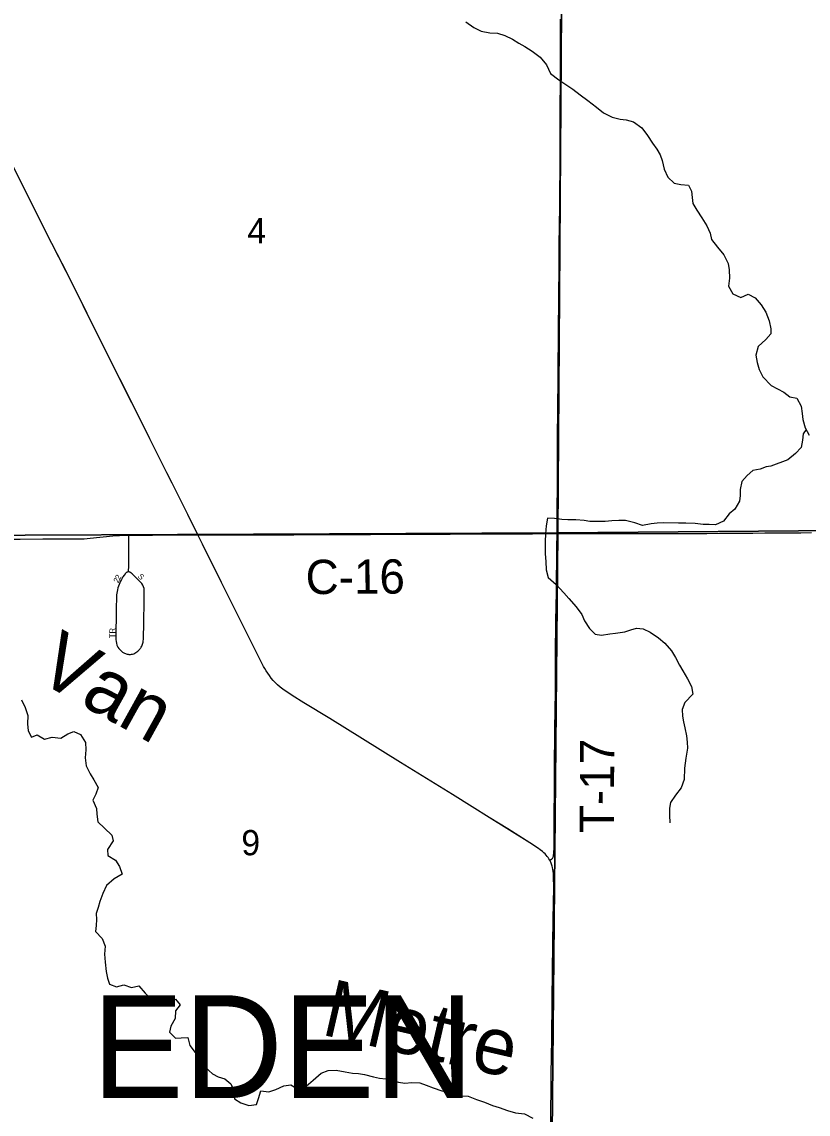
# Model space of a CAD drawing. Extents: x 0 to 34, y 0 to 22.
# Drawn here: x 6.531 to 7.184, y 16.419 to 17.325 of the extents above; entities that cross this region are included whole.
import ezdxf

# ---------------------------------------------------------------- set-up
doc = ezdxf.new("R2010")
doc.units = 0
for name, color, linetype in [('Default', 7, 'Continuous'), ('GM_X_County_Road', 7, 'Continuous'), ('GM_X_County_Road_Text', 7, 'Continuous'), ('GM_X_Minor_River', 7, 'Continuous'), ('GM_X_Minor_River_Text', 7, 'Continuous'), ('GM_X_Section', 7, 'Continuous'), ('GM_X_Section_Text', 7, 'Continuous'), ('GM_X_State_Route', 7, 'Continuous'), ('GM_X_Township_Road', 7, 'Continuous'), ('GM_X_Township_Road_Text', 7, 'Continuous'), ('GM_X_Township_Subdivision', 7, 'Continuous'), ('GM_X_Township_Subdivision_Text', 7, 'Continuous'), ('GM_X_Township_Text', 7, 'Continuous')]:
    doc.layers.add(name, color=color, linetype=linetype)

msp = doc.modelspace()

# ---------------------------------------------------------------- linework, layer by layer
at = {"layer": 'Default'}
for points in [[(6.91883, 16.66544), (6.9048, 16.67409), (6.88846, 16.6843), (6.84537, 16.71094), (6.81393, 16.73042), (6.78677, 16.74735), (6.76527, 16.76044), (6.75546, 16.76648), (6.7478, 16.77167), (6.74556, 16.77341), (6.74352, 16.7752), (6.74185, 16.77684), (6.73992, 16.77887), (6.73824, 16.78079), (6.73664, 16.7829), (6.73525, 16.78496), (6.73408, 16.78675), (6.73286, 16.78871), (6.73182, 16.79045), (6.73097, 16.79206), (6.72699, 16.79994), (6.72252, 16.80879), (6.71822, 16.81742), (6.71488, 16.82408), (6.70988, 16.8341), (6.7025, 16.84894), (6.69702, 16.85996), (6.68994, 16.87423), (6.68404, 16.88612), (6.68111, 16.89197), (6.67731, 16.89961), (6.6689, 16.91658), (6.66233, 16.92968), (6.65593, 16.94252), (6.65174, 16.95091), (6.6375, 16.9793), (6.62776, 16.99872), (6.59751, 17.059), (6.57379, 17.10651), (6.55629, 17.14119), (6.53311, 17.18728), (6.52382, 17.20557)], [(6.97007, 16.40192), (6.97021, 16.4214), (6.97034, 16.44107), (6.97042, 16.4528), (6.97093, 16.48138), (6.97129, 16.51432), (6.97169, 16.56094), (6.97196, 16.58083), (6.97247, 16.60756), (6.97241, 16.61624), (6.97231, 16.61859), (6.97208, 16.62085), (6.97187, 16.62233), (6.97156, 16.62388), (6.97129, 16.62494), (6.97101, 16.62593), (6.97049, 16.62738), (6.9699, 16.62876), (6.96932, 16.62986), (6.96855, 16.63115), (6.96789, 16.63213), (6.96713, 16.63312), (6.96628, 16.63411), (6.96529, 16.63516), (6.96423, 16.63617), (6.96303, 16.63721), (6.96135, 16.63847), (6.95981, 16.6396), (6.95256, 16.64437), (6.93429, 16.65584), (6.91883, 16.66544)]]:
    msp.add_lwpolyline(points, dxfattribs=at)
at = {"layer": 'GM_X_County_Road'}
for points in [[(6.47162, 16.8974), (6.47313, 16.89712), (6.47501, 16.89685), (6.47643, 16.89667), (6.47767, 16.89652), (6.47946, 16.89634), (6.48126, 16.89619), (6.48339, 16.89608), (6.48643, 16.89593), (6.49157, 16.89586), (6.50071, 16.89594), (6.52992, 16.8961), (6.54887, 16.89625), (6.56099, 16.89624), (6.57653, 16.89625), (6.58303, 16.89641), (6.58796, 16.89676), (6.60683, 16.89871), (6.61243, 16.89907), (6.62003, 16.89925)], [(6.62003, 16.89925), (6.62456, 16.89935), (6.63978, 16.89939), (6.65094, 16.89953), (6.67117, 16.89958), (6.67556, 16.89959), (6.67731, 16.89961)], [(6.67731, 16.89961), (6.69531, 16.89963), (6.71149, 16.89965), (6.73144, 16.89955), (6.75684, 16.89966), (6.76959, 16.8998), (6.79388, 16.89988), (6.82056, 16.89997), (6.85258, 16.90027), (6.88646, 16.90029), (6.90449, 16.90039), (6.92096, 16.90037), (6.94022, 16.90045), (6.95482, 16.90052), (6.9754, 16.90057)], [(6.9754, 16.90057), (6.98031, 16.90059), (6.99678, 16.90076), (7.01917, 16.90073), (7.04154, 16.90075), (7.07325, 16.90079), (7.08537, 16.90081), (7.09034, 16.9008), (7.09936, 16.90081), (7.10992, 16.9009), (7.11645, 16.90093), (7.12204, 16.90096), (7.12732, 16.90101), (7.1326, 16.90107), (7.13757, 16.9011), (7.14749, 16.90114), (7.16111, 16.90116), (7.16916, 16.90122), (7.17752, 16.90137), (7.18621, 16.90148)]]:
    msp.add_lwpolyline(points, dxfattribs=at)
at = {"layer": 'GM_X_Minor_River'}
for points in [[(6.89965, 17.3248), (6.90626, 17.32001), (6.91231, 17.31693), (6.91951, 17.31555), (6.92596, 17.31531), (6.93201, 17.31337), (6.93825, 17.31029), (6.94354, 17.30702), (6.94846, 17.30433), (6.9545, 17.30049), (6.96129, 17.2955), (6.96637, 17.28921), (6.96992, 17.28197), (6.97671, 17.27661), (6.98181, 17.27353), (6.98823, 17.26893), (6.99446, 17.26433), (7.00087, 17.25954), (7.00785, 17.25399), (7.0137, 17.24939), (7.02107, 17.24573), (7.02751, 17.24416), (7.03244, 17.24356), (7.03869, 17.2418), (7.04548, 17.23682), (7.05018, 17.23052), (7.0543, 17.22423), (7.05787, 17.21927), (7.06087, 17.21451)], [(7.06087, 17.21451), (7.06236, 17.20975), (7.06401, 17.20272), (7.067, 17.19606), (7.07246, 17.19109), (7.07796, 17.18991), (7.08421, 17.18929), (7.08665, 17.18453), (7.08736, 17.17921), (7.08771, 17.17409), (7.09108, 17.16856), (7.09521, 17.16246), (7.09952, 17.1556), (7.10213, 17.14951), (7.10342, 17.14438), (7.10831, 17.13789), (7.11357, 17.13159), (7.11713, 17.12436), (7.11785, 17.11923), (7.11817, 17.11221), (7.11755, 17.10558), (7.12111, 17.09929), (7.12773, 17.09639), (7.13382, 17.099), (7.13949, 17.09612), (7.14457, 17.0902), (7.14832, 17.0841), (7.15112, 17.07706), (7.15244, 17.07034), (7.15244, 17.06628), (7.14834, 17.06153), (7.14204, 17.05569), (7.14009, 17.0485), (7.14118, 17.04242), (7.14285, 17.03672), (7.14602, 17.03044), (7.1529, 17.0234)], [(7.1529, 17.0234), (7.16324, 17.01773), (7.16816, 17.01411), (7.17423, 17.01294), (7.17761, 17.00629), (7.17854, 17.00003), (7.17908, 16.99509), (7.18114, 16.98825), (7.18434, 16.98217)], [(7.18179, 16.98702), (7.17922, 16.98333), (7.17882, 16.97802), (7.17765, 16.97195), (7.17289, 16.96704), (7.1666, 16.96175), (7.15242, 16.95642)], [(7.15242, 16.95642), (7.14869, 16.95587), (7.14375, 16.95401), (7.13767, 16.95292), (7.13289, 16.94879), (7.12849, 16.94389), (7.12711, 16.93707), (7.12708, 16.93233), (7.12647, 16.92759), (7.12263, 16.92098), (7.11786, 16.91703), (7.11326, 16.911), (7.10659, 16.90783), (7.10147, 16.90805), (7.09654, 16.90828), (7.0899, 16.9089), (7.08213, 16.90915), (7.07587, 16.90938), (7.06316, 16.90948), (7.05822, 16.90933), (7.05329, 16.9088), (7.04606, 16.90733), (7.03963, 16.90947), (7.03187, 16.91161), (7.02636, 16.91146), (7.02067, 16.91113), (7.01516, 16.9106), (7.00245, 16.9107), (6.99771, 16.91149), (6.99089, 16.91192), (6.98406, 16.91216), (6.97913, 16.91239), (6.97306, 16.91319), (6.96718, 16.91343), (6.96618, 16.90699), (6.96557, 16.90035), (6.96533, 16.8941), (6.96548, 16.88935), (6.96544, 16.88385), (6.96596, 16.8774), (6.9661, 16.87057), (6.96795, 16.8643), (6.97455, 16.85856), (6.98076, 16.85149), (6.9849, 16.84672), (6.99111, 16.84004), (6.9958, 16.83355), (6.99804, 16.82842), (7.00216, 16.82194), (7.00687, 16.81716), (7.01199, 16.81636), (7.01902, 16.81764), (7.02377, 16.81817), (7.03155, 16.81925), (7.03631, 16.82092), (7.04125, 16.82221), (7.04656, 16.82179), (7.05242, 16.8189), (7.05941, 16.81411), (7.06449, 16.80971), (7.07014, 16.80341), (7.07351, 16.79807), (7.07688, 16.7916), (7.0795, 16.78683), (7.08344, 16.78017), (7.08661, 16.77388), (7.08789, 16.76743), (7.0812, 16.76065), (7.07907, 16.75479), (7.07941, 16.74928), (7.08013, 16.74454), (7.08123, 16.7396), (7.0827, 16.73295), (7.08323, 16.72782), (7.08338, 16.7227), (7.08218, 16.71437), (7.08098, 16.70622), (7.08053, 16.69674), (7.0782, 16.68993), (7.07361, 16.68389), (7.06939, 16.67786), (7.0684, 16.67293), (7.06855, 16.66724), (7.06869, 16.66079)], [(6.531, 16.76271), (6.53418, 16.75642), (6.5364, 16.74977), (6.53616, 16.74294), (6.5365, 16.73725), (6.53931, 16.73192), (6.54406, 16.73378), (6.55011, 16.73013), (6.55638, 16.73198), (6.56377, 16.73097), (6.56949, 16.73453), (6.57444, 16.73658), (6.58011, 16.73408), (6.58424, 16.7276), (6.58438, 16.72152), (6.58377, 16.71489), (6.58466, 16.70806), (6.58803, 16.70158), (6.59103, 16.69644), (6.59477, 16.69015), (6.59284, 16.68467), (6.59033, 16.67975), (6.59332, 16.6729), (6.59366, 16.66797), (6.59437, 16.6617), (6.60002, 16.65654), (6.60605, 16.6508), (6.60696, 16.64587), (6.60236, 16.63888), (6.6027, 16.63376), (6.60893, 16.62992), (6.61231, 16.62477), (6.61454, 16.61831), (6.60787, 16.61456), (6.60157, 16.60892), (6.59848, 16.6023), (6.59597, 16.59568), (6.5946, 16.59076), (6.59286, 16.58584), (6.5932, 16.58072), (6.59297, 16.57579), (6.59237, 16.57086), (6.59801, 16.56513), (6.60043, 16.55866), (6.59981, 16.55203), (6.60052, 16.54539), (6.60142, 16.53779), (6.60251, 16.53228), (6.60418, 16.52715), (6.60986, 16.52502), (6.61594, 16.52668), (6.62219, 16.52455), (6.62846, 16.52583), (6.63354, 16.51972)], [(6.63354, 16.51972), (6.63938, 16.51418), (6.64678, 16.51526), (6.65322, 16.51388), (6.65873, 16.51479), (6.66268, 16.51002), (6.65866, 16.50512), (6.65842, 16.49867), (6.65496, 16.49243), (6.65379, 16.48732), (6.65868, 16.48254), (6.66362, 16.4827), (6.66893, 16.48304), (6.67059, 16.47638), (6.6751, 16.47047), (6.67998, 16.46398), (6.68336, 16.45846), (6.68939, 16.45291), (6.6943, 16.45041), (6.69979, 16.44885), (6.70469, 16.44464), (6.70768, 16.43836), (6.70783, 16.4321), (6.71292, 16.42883), (6.71974, 16.42651), (6.72601, 16.42741), (6.72775, 16.43233), (6.7295, 16.43876), (6.73614, 16.43795), (6.74204, 16.44), (6.7487, 16.44298), (6.7544, 16.4437), (6.76063, 16.44024), (6.7671, 16.44265), (6.77302, 16.44773), (6.7797, 16.45356), (6.78541, 16.4556), (6.79205, 16.45593), (6.79944, 16.45455), (6.8057, 16.45355), (6.81063, 16.45314), (6.81555, 16.45234), (6.82294, 16.45039), (6.82786, 16.4494), (6.83317, 16.44861), (6.83847, 16.44724), (6.84377, 16.44606), (6.84908, 16.44526), (6.85478, 16.4456), (6.86141, 16.44536), (6.86671, 16.44361), (6.87258, 16.44129), (6.87977, 16.43877), (6.88488, 16.43778), (6.89113, 16.43527), (6.89605, 16.43467), (6.90156, 16.43443), (6.90837, 16.43173), (6.91499, 16.4294), (6.9218, 16.42669), (6.9271, 16.42495), (6.9341, 16.42262), (6.94073, 16.42067), (6.94812, 16.41967), (6.95511, 16.4162)]]:
    msp.add_lwpolyline(points, dxfattribs=at)
at = {"layer": 'GM_X_Section'}
for points in [[(6.47745, 17.41541), (6.48295, 17.41537), (6.97935, 17.41426), (6.97584, 16.9012), (6.47069, 16.89897)], [(6.97935, 17.41426), (7.47845, 17.4078), (7.47479, 16.90534), (6.97584, 16.9012)], [(6.97584, 16.9012), (7.47479, 16.90534), (7.46886, 16.40612), (6.9711, 16.40274)], [(6.97584, 16.9012), (6.9711, 16.40274), (6.46804, 16.39936), (6.47069, 16.89897)]]:
    msp.add_lwpolyline(points, close=True, dxfattribs=at)
at = {"layer": 'GM_X_State_Route'}
for points in [[(6.67731, 16.89961), (6.67407, 16.90615), (6.6689, 16.91658), (6.66233, 16.92968), (6.65593, 16.94252), (6.65174, 16.95091), (6.6375, 16.9793), (6.62776, 16.99872), (6.61742, 17.01925), (6.59751, 17.059), (6.59057, 17.07286), (6.57379, 17.10651), (6.56473, 17.12448), (6.55629, 17.14119), (6.54692, 17.15979), (6.53311, 17.18728), (6.52382, 17.20557), (6.51664, 17.22004), (6.50402, 17.24466), (6.49005, 17.27243), (6.48211, 17.28826), (6.4784, 17.29558), (6.46989, 17.31238), (6.45232, 17.34668)], [(6.97008, 16.40384), (6.97021, 16.4214), (6.97034, 16.44107), (6.97042, 16.4528), (6.97093, 16.48138), (6.97129, 16.51432), (6.97169, 16.56094), (6.97196, 16.58083), (6.97247, 16.60756), (6.97241, 16.61624), (6.97231, 16.61859), (6.97208, 16.62085), (6.97187, 16.62233), (6.97156, 16.62388), (6.97129, 16.62494), (6.97101, 16.62593), (6.97049, 16.62738), (6.9699, 16.62876), (6.96932, 16.62986), (6.96855, 16.63115), (6.96789, 16.63213), (6.96713, 16.63312), (6.96628, 16.63411), (6.96529, 16.63516), (6.96423, 16.63617), (6.96303, 16.63721), (6.96135, 16.63847), (6.95981, 16.6396), (6.95256, 16.64437), (6.91883, 16.66544), (6.9048, 16.67409), (6.88846, 16.6843), (6.84537, 16.71094), (6.81393, 16.73042), (6.78677, 16.74735), (6.76527, 16.76044), (6.75546, 16.76648), (6.75026, 16.76993), (6.7478, 16.77167), (6.74556, 16.77341), (6.74352, 16.7752), (6.74185, 16.77684), (6.73992, 16.77887), (6.73824, 16.78079), (6.73664, 16.7829), (6.73525, 16.78496), (6.73408, 16.78675), (6.73286, 16.78871), (6.73182, 16.79045), (6.73097, 16.79206), (6.72699, 16.79994), (6.72252, 16.80879), (6.71822, 16.81742), (6.71488, 16.82408), (6.70988, 16.8341), (6.7025, 16.84894), (6.69702, 16.85996), (6.68994, 16.87423), (6.68404, 16.88612), (6.68111, 16.89197), (6.67731, 16.89961)]]:
    msp.add_lwpolyline(points, dxfattribs=at)
at = {"layer": 'GM_X_Township_Road'}
for points in [[(6.9754, 16.90057), (6.97544, 16.91303), (6.9754, 16.91925), (6.97542, 16.92795), (6.97547, 16.93292), (6.97554, 16.941), (6.97562, 16.95002), (6.97564, 16.9553), (6.97563, 16.97021), (6.97571, 16.9842), (6.97595, 16.99943), (6.97617, 17.03393), (6.97629, 17.04792), (6.97631, 17.05382), (6.97638, 17.06066), (6.97642, 17.06688), (6.9765, 17.07589), (6.97662, 17.0877), (6.97666, 17.09081), (6.97668, 17.09578), (6.97677, 17.10417), (6.97692, 17.11473), (6.97697, 17.1225), (6.97704, 17.1284), (6.97709, 17.13742), (6.97736, 17.15824), (6.97743, 17.16943), (6.97748, 17.17223), (6.97747, 17.17564), (6.9775, 17.17844), (6.97745, 17.18432), (6.97758, 17.18867), (6.9777, 17.19831), (6.97775, 17.2039), (6.97777, 17.21011), (6.97776, 17.21664), (6.9777, 17.22254), (6.97772, 17.22844), (6.97775, 17.23434), (6.9778, 17.23962), (6.97779, 17.2452), (6.97783, 17.25172), (6.97788, 17.25669), (6.97791, 17.26228), (6.97798, 17.26631), (6.97804, 17.27439), (6.97812, 17.2924), (6.9782, 17.30886), (6.97816, 17.31414), (6.97814, 17.32159), (6.97814, 17.32687)], [(6.96932, 16.62986), (6.97059, 16.63074), (6.97101, 16.63104), (6.97133, 16.6314), (6.97165, 16.63184), (6.97189, 16.63235), (6.97204, 16.63284), (6.97217, 16.63337), (6.97231, 16.63401), (6.9724, 16.63459), (6.97251, 16.63529), (6.97264, 16.63676), (6.97273, 16.63952), (6.97275, 16.64761), (6.97286, 16.66626), (6.97302, 16.68864), (6.97316, 16.70449), (6.97343, 16.73868), (6.97382, 16.76945), (6.97407, 16.79992), (6.97436, 16.82819), (6.97467, 16.85213), (6.97519, 16.8888), (6.9754, 16.90057)]]:
    msp.add_lwpolyline(points, dxfattribs=at)
at = {"layer": 'GM_X_Township_Subdivision'}
for points in [[(6.61982, 16.86888), (6.62006, 16.87409), (6.62018, 16.8772), (6.62017, 16.88151), (6.62013, 16.88788), (6.62006, 16.89726), (6.62003, 16.89925)], [(6.61982, 16.86888), (6.61939, 16.86883), (6.61899, 16.86877), (6.61862, 16.86865), (6.61828, 16.86849), (6.6179, 16.86826), (6.61749, 16.86793), (6.61693, 16.86726), (6.61618, 16.86623), (6.61521, 16.86474), (6.61461, 16.86379), (6.61395, 16.8626), (6.61325, 16.86127), (6.61257, 16.85982), (6.61199, 16.85851), (6.61145, 16.85693), (6.61102, 16.85555), (6.61061, 16.85395), (6.61034, 16.85259), (6.61015, 16.85128), (6.60996, 16.84988), (6.60986, 16.84852), (6.6097, 16.83786), (6.60956, 16.82959), (6.60943, 16.82167), (6.60932, 16.81586), (6.60931, 16.81278), (6.60945, 16.81126), (6.60973, 16.80974), (6.61021, 16.8081), (6.611, 16.80657), (6.61186, 16.80531), (6.61278, 16.80428), (6.61423, 16.80287), (6.61496, 16.80237), (6.61583, 16.80185), (6.6166, 16.80148), (6.61731, 16.80116), (6.61795, 16.80095), (6.61869, 16.80074), (6.6194, 16.80062), (6.6201, 16.80055), (6.62082, 16.80051), (6.6216, 16.80055), (6.6223, 16.8006), (6.62317, 16.80076), (6.6241, 16.8011), (6.62501, 16.80153), (6.62596, 16.8021), (6.62675, 16.8026), (6.62742, 16.80312), (6.62804, 16.8037), (6.62861, 16.80425), (6.62914, 16.80483), (6.62955, 16.80535), (6.62998, 16.80598), (6.63037, 16.80661), (6.63079, 16.80731), (6.6311, 16.80806), (6.63144, 16.80891), (6.63168, 16.80971), (6.63194, 16.81064), (6.6321, 16.81166), (6.63227, 16.81286), (6.63236, 16.81407), (6.63264, 16.82633), (6.6328, 16.8451), (6.63287, 16.85317), (6.63267, 16.85502), (6.63228, 16.85652), (6.63163, 16.85792), (6.63076, 16.8592), (6.62951, 16.86058), (6.62756, 16.86255), (6.62605, 16.86409), (6.62477, 16.86545), (6.62276, 16.8674), (6.62216, 16.86789), (6.62171, 16.86827), (6.62122, 16.86852), (6.62084, 16.86869), (6.62034, 16.86882), (6.61982, 16.86888)]]:
    msp.add_lwpolyline(points, dxfattribs=at)

# ---------------------------------------------------------------- texts
at = {"layer": 'GM_X_County_Road_Text'}
msp.add_text('C-16', height=0.028409, rotation=0.34851, dxfattribs=at).set_placement((6.76679, 16.85044))
at = {"layer": 'GM_X_Minor_River_Text'}
for s, height, rotation, p in [('Van', 0.047361, 331.01861, (6.54145, 16.78028)), ('Metre', 0.047365, 347.01695, (6.77861, 16.48565))]:
    msp.add_text(s, height=height, rotation=rotation, dxfattribs=at).set_placement(p)
at = {"layer": 'GM_X_Section_Text'}
for s, p in [('4', (6.71841, 17.14124)), ('9', (6.71341, 16.634))]:
    msp.add_text(s, height=0.02093, rotation=0.00001, dxfattribs=at).set_placement(p)
at = {"layer": 'GM_X_Township_Road_Text'}
msp.add_text('T-17', height=0.028409, rotation=89.65422, dxfattribs=at).set_placement((7.0223, 16.65225))
at = {"layer": 'GM_X_Township_Subdivision_Text'}
for s, height, rotation, p in [('2', 0.00473, 62.37377, (6.61253, 16.86191)), ('S', 0.00473, 314.58814, (6.62715, 16.86479)), ('2', 0.00473, 65.29246, (6.61134, 16.85931)), ('TR', 0.004735, 90, (6.60877, 16.81397))]:
    msp.add_text(s, height=height, rotation=rotation, dxfattribs=at).set_placement(p)
at = {"layer": 'GM_X_Township_Text'}
msp.add_text('EDEN', height=0.085227, rotation=0.00001, dxfattribs=at).set_placement((6.58953, 16.43279))

doc.saveas('drawing.dxf')
